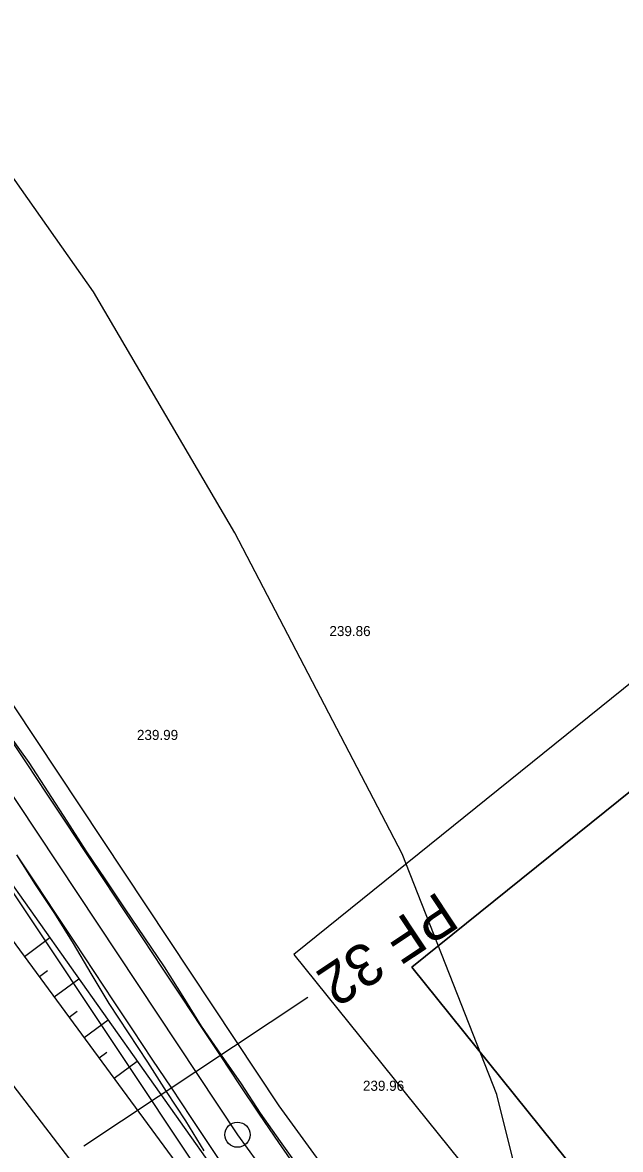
# Model space of a CAD drawing. Extents: x -555887 to -552101, y -1100251 to -1096546.
# Drawn here: x -555600.7 to -555565.1, y -1098746 to -1098679 of the extents above; entities that cross this region are included whole.
import ezdxf

# ---------------------------------------------------------------- set-up
doc = ezdxf.new("R2010")
doc.units = 0
for name, color, linetype in [('PARCELY_cesty', 7, 'Continuous'), ('PARCELY_VHO', 7, 'Continuous'), ('POLYGONY_SITUACE_PF', 7, 'Continuous'), ('POLYGONY_SITUACE_PF_POPISY', 7, 'Continuous'), ('POLYGONY_SITUACE_PO', 7, 'Continuous'), ('ram_VC3-R', 7, 'Continuous'), ('vrstevnice', 7, 'Continuous'), ('Výškopis', 7, 'Continuous'), ('ZSST', 7, 'Continuous')]:
    doc.layers.add(name, color=color, linetype=linetype)

msp = doc.modelspace()

# ---------------------------------------------------------------- linework, layer by layer
at = {"layer": 'PARCELY_cesty'}
for points in [[(-555750.86, -1098506.27), (-555731.02, -1098536.03), (-555579.56, -1098763.26), (-555574.359, -1098768.083), (-555567.523, -1098773.632), (-555557.756, -1098780.668), (-555551.79, -1098781.79), (-555519.524, -1098802.113), (-555513.631, -1098805.205), (-555507.213, -1098807.372), (-555500.534, -1098808.504), (-555493.761, -1098808.573), (-555487.06, -1098807.578), (-555480.599, -1098805.544), (-555474.537, -1098802.52), (-555469.026, -1098798.582), (-555464.285, -1098793.91), (-555430.01, -1098754.35)], [(-555724.98, -1098533.23), (-555585.414, -1098743.408), (-555580.559, -1098750.089), (-555575.199, -1098756.288), (-555569.335, -1098762.012), (-555563.009, -1098767.221), (-555556.213, -1098771.913), (-555516.527, -1098796.91), (-555511.263, -1098799.672), (-555505.743, -1098801.535), (-555499.999, -1098802.509), (-555494.173, -1098802.569), (-555488.41, -1098801.713), (-555482.853, -1098799.963), (-555477.64, -1098797.362), (-555472.899, -1098793.975), (-555468.665, -1098789.803), (-555432.8, -1098748.4)]]:
    msp.add_lwpolyline(points, dxfattribs=at)
at = {"layer": 'PARCELY_VHO'}
msp.add_lwpolyline([(-555757.22, -1098510.28), (-555752.5, -1098508.06), (-555750.86, -1098506.27), (-555731.02, -1098536.03), (-555579.56, -1098763.26), (-555581.632, -1098777.843), (-555591.69, -1098762.26), (-555630.72, -1098700.04), (-555680.24, -1098620.98), (-555692.89, -1098600.93), (-555699.02, -1098592.11), (-555708.39, -1098577.04), (-555756.35, -1098525.17)], close=True, dxfattribs=at)
at = {"layer": 'POLYGONY_SITUACE_PF'}
for p, q in [((-555583.693, -1098736.962), (-555590.357, -1098741.387)), ((-555590.357, -1098741.387), (-555597.022, -1098745.812))]:
    msp.add_line(p, q, dxfattribs=at)
at = {"layer": 'POLYGONY_SITUACE_PO'}
for p, q in [((-555725.052, -1098538.542), (-555587.878, -1098745.121)), ((-555601.576, -1098721.328), (-555600.424, -1098723.063)), ((-555601.576, -1098721.328), (-555600.424, -1098723.063)), ((-555601.517, -1098721.288), (-555600.297, -1098722.979)), ((-555600.424, -1098723.063), (-555599.271, -1098724.799)), ((-555600.424, -1098723.063), (-555599.271, -1098724.799)), ((-555600.297, -1098722.979), (-555599.167, -1098724.73)), ((-555599.167, -1098724.73), (-555598.035, -1098726.479)), ((-555599.271, -1098724.799), (-555598.119, -1098726.535)), ((-555599.271, -1098724.799), (-555598.119, -1098726.535)), ((-555598.119, -1098726.535), (-555596.967, -1098728.27)), ((-555598.119, -1098726.535), (-555596.967, -1098728.27)), ((-555598.035, -1098726.479), (-555596.906, -1098728.23)), ((-555601.035, -1098728.471), (-555599.882, -1098730.206)), ((-555601.035, -1098728.471), (-555599.92, -1098730.231)), ((-555596.967, -1098728.27), (-555595.814, -1098730.006)), ((-555596.967, -1098728.27), (-555595.814, -1098730.006)), ((-555596.906, -1098728.23), (-555595.743, -1098729.958)), ((-555595.814, -1098730.006), (-555594.662, -1098731.741)), ((-555595.814, -1098730.006), (-555594.662, -1098731.741)), ((-555595.743, -1098729.958), (-555594.584, -1098731.689)), ((-555599.92, -1098730.231), (-555598.772, -1098731.97)), ((-555599.882, -1098730.206), (-555598.73, -1098731.942)), ((-555598.772, -1098731.97), (-555597.671, -1098733.74)), ((-555598.73, -1098731.942), (-555597.577, -1098733.677)), ((-555594.662, -1098731.741), (-555593.509, -1098733.477)), ((-555594.662, -1098731.741), (-555593.509, -1098733.477)), ((-555594.584, -1098731.689), (-555593.422, -1098733.419)), ((-555593.422, -1098733.419), (-555592.252, -1098735.143)), ((-555597.671, -1098733.74), (-555596.608, -1098735.535)), ((-555597.577, -1098733.677), (-555596.425, -1098735.413)), ((-555593.509, -1098733.477), (-555592.357, -1098735.212)), ((-555593.509, -1098733.477), (-555592.357, -1098735.212)), ((-555596.425, -1098735.413), (-555595.272, -1098737.148)), ((-555592.357, -1098735.212), (-555591.204, -1098736.948)), ((-555592.357, -1098735.212), (-555591.204, -1098736.948)), ((-555592.252, -1098735.143), (-555591.128, -1098736.897)), ((-555596.608, -1098735.535), (-555595.539, -1098737.326)), ((-555595.539, -1098737.326), (-555594.378, -1098739.055)), ((-555595.272, -1098737.148), (-555594.12, -1098738.884)), ((-555591.204, -1098736.948), (-555590.052, -1098738.683)), ((-555591.204, -1098736.948), (-555590.052, -1098738.683)), ((-555591.128, -1098736.897), (-555590.031, -1098738.67)), ((-555590.052, -1098738.683), (-555588.899, -1098740.419)), ((-555590.052, -1098738.683), (-555588.899, -1098740.419)), ((-555590.031, -1098738.67), (-555588.851, -1098740.387)), ((-555594.378, -1098739.055), (-555593.243, -1098740.802)), ((-555594.12, -1098738.884), (-555592.968, -1098740.619)), ((-555593.243, -1098740.802), (-555592.123, -1098742.56)), ((-555592.968, -1098740.619), (-555591.815, -1098742.355)), ((-555588.899, -1098740.419), (-555587.747, -1098742.154)), ((-555588.899, -1098740.419), (-555587.747, -1098742.154)), ((-555588.851, -1098740.387), (-555587.648, -1098742.089)), ((-555587.747, -1098742.154), (-555586.594, -1098743.89)), ((-555587.747, -1098742.154), (-555586.594, -1098743.89)), ((-555587.648, -1098742.089), (-555586.532, -1098743.848)), ((-555592.123, -1098742.56), (-555590.967, -1098744.293)), ((-555591.815, -1098742.355), (-555590.663, -1098744.091)), ((-555590.663, -1098744.091), (-555589.51, -1098745.826)), ((-555586.594, -1098743.89), (-555585.442, -1098745.588)), ((-555586.594, -1098743.89), (-555585.442, -1098745.588)), ((-555586.532, -1098743.848), (-555585.339, -1098745.517)), ((-555590.967, -1098744.293), (-555589.881, -1098746.072)), ((-555587.878, -1098745.121), (-555582.911, -1098751.955)), ((-555585.339, -1098745.517), (-555584.153, -1098747.182)), ((-555589.51, -1098745.826), (-555588.323, -1098747.576)), ((-555585.442, -1098745.588), (-555584.262, -1098747.261)), ((-555585.442, -1098745.588), (-555584.262, -1098747.261))]:
    msp.add_line(p, q, dxfattribs=at)
msp.add_circle((-555587.878, -1098745.121), 0.75, dxfattribs=at)
at = {"layer": 'ram_VC3-R'}
for points in [[(-554580.57, -1098306.86), (-554766.919, -1098075.596), (-555584.519, -1098734.405), (-555398.17, -1098965.669), (-554580.57, -1098306.86)], [(-555397.414, -1098958.639), (-555577.489, -1098735.161), (-554767.675, -1098082.626), (-554587.601, -1098306.104), (-555397.414, -1098958.639)]]:
    msp.add_lwpolyline(points, dxfattribs=at)
for points in [[(-554580.57, -1098306.86), (-554766.919, -1098075.596), (-555584.519, -1098734.405), (-555398.17, -1098965.669)], [(-554587.601, -1098306.104), (-554767.675, -1098082.626), (-555577.489, -1098735.161), (-555397.414, -1098958.639)]]:
    msp.add_lwpolyline(points, close=True, dxfattribs=at)
at = {"layer": 'vrstevnice'}
for points in [[(-555678.458, -1098878.537), (-555667.931, -1098877.99), (-555649.403, -1098864.653), (-555636.297, -1098849.734), (-555609.408, -1098826.452), (-555591.333, -1098811.082), (-555575.249, -1098799.18), (-555569.909, -1098789.63), (-555567.949, -1098780.08), (-555568.369, -1098765.76), (-555570.189, -1098751.72), (-555572.439, -1098742.73), (-555578.059, -1098728.41), (-555588.029, -1098709.31), (-555596.449, -1098694.99), (-555606.559, -1098680.67), (-555643.909, -1098636.3)], [(-555667.931, -1098877.99), (-555649.403, -1098864.653), (-555636.297, -1098849.734), (-555609.408, -1098826.452), (-555591.333, -1098811.082), (-555575.249, -1098799.18), (-555569.909, -1098789.63), (-555567.949, -1098780.08), (-555568.369, -1098765.76), (-555570.189, -1098751.72), (-555572.439, -1098742.73), (-555578.059, -1098728.41), (-555588.029, -1098709.31), (-555596.449, -1098694.99), (-555606.559, -1098680.67), (-555643.909, -1098636.3)]]:
    msp.add_lwpolyline(points, dxfattribs=at)
at = {"layer": 'ZSST'}
for p, q in [((-555600.566, -1098734.512), (-555599.055, -1098733.398)), ((-555599.677, -1098735.719), (-555599.181, -1098735.354)), ((-555598.787, -1098736.927), (-555597.32, -1098735.846)), ((-555597.897, -1098738.135), (-555597.416, -1098737.78)), ((-555597.007, -1098739.342), (-555595.584, -1098738.294)), ((-555596.118, -1098740.55), (-555595.651, -1098740.206)), ((-555595.228, -1098741.758), (-555593.848, -1098740.741))]:
    msp.add_line(p, q, dxfattribs=at)
for points in [[(-555583.09, -1098783.14), (-555578.35, -1098765.76), (-555579.94, -1098761.61), (-555586.95, -1098750.47), (-555602.11, -1098729.09), (-555610.49, -1098716.56), (-555625.36, -1098695.37), (-555647.98, -1098661.72), (-555663.92, -1098637.15), (-555690.5, -1098596.36), (-555718.88, -1098552.89), (-555735.07, -1098529.28), (-555745.86, -1098513.94), (-555753.49, -1098503.56), (-555763.78, -1098488.05)], [(-555597.41, -1098802.89), (-555591.55, -1098792.17), (-555588.34, -1098782.12), (-555587.08, -1098768.67), (-555587.87, -1098760.95), (-555588.33, -1098751.12), (-555603.78, -1098730.15)], [(-555599.42, -1098802.22), (-555594.19, -1098791.75), (-555591.22, -1098781.38), (-555590.79, -1098768.58), (-555592.18, -1098757.93), (-555594.54, -1098750.89), (-555608.61, -1098732.6)]]:
    msp.add_lwpolyline(points, dxfattribs=at)

# ---------------------------------------------------------------- texts
at = {"layer": 'POLYGONY_SITUACE_PF_POPISY'}
msp.add_text('PF 32', height=2.5, rotation=213.58538, dxfattribs=at).set_placement((-555575.915, -1098730.597))
at = {"layer": 'Výškopis'}
for s, p in [('239.86', (-555582.402, -1098715.46)), ('239.99', (-555593.864, -1098721.64)), ('239.96', (-555580.404, -1098742.51))]:
    msp.add_text(s, height=0.6, dxfattribs=at).set_placement(p)

doc.saveas('drawing.dxf')
